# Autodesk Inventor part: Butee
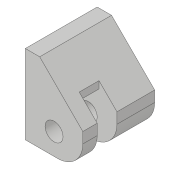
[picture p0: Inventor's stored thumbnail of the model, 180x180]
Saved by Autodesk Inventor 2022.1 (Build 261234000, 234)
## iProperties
Created: 2018-06
Part Number: Butee
Material: Générique
Document SubType Name: Modeling
Designer: Fabian Perrée
Density: 1 g/cm^3
Appearance: Par défaut
Mass: 4.03257 g
Surface Area: 22.3212 cm^2
Volume: 4.03257 cm^3
Author: Fabian Perrée
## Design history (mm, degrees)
sketch "Esquisse1"
  geometry: L1 (0, 0)-(0, 13); L2 (0, 22)-(4, 22); L3 (4, 22)-(11, 15); L4 (16, 10)-(16, 0); L5 (16, 0)-(0, 0); L6 (0, 13)-(11, 13); L7 (11, 13)-(11, 15); L8 (11, 15)-(16, 10); L9 (0, 13)-(0, 22); C1 r 2.5 at (8, 6)
  constraints: 18 end point, 4 perpendicular, 2 parallel, 2 vertical, 1 centre point, 1 collinear, 1 horizontal
  dimensions: "d1" = 4 distance of L2.start L2.end; "d2" = 135 deg angle of L2 L3; "d3" = 5 diameter of C1; "d4" = 6 distance from line of L5 C1.centre; "d5" = 8 distance from line of L1 C1.centre; "d9" = 3 distance from line of C1.centre L7; "d18" = 13 distance between parallel lines of L5 L6; "d20" = 16 distance from line of L2 C1.centre; "d21" = 16 distance between parallel lines of L4 L1
extrude "Extrusion1" new body sketch "Esquisse1" distance "d10" = 4; taper "d12" = 0 deg; dims "d11" = 16, "d13" = 0
extrude "Extrusion2" join sketch "Esquisse1" distance "d14" = 4; taper "d15" = 0 deg
node "Plan de construction1"
node "Plan de construction2"
extrude "Extrusion3" join sketch "Esquisse1" stored distance "d16" = 10; taper "d17" = 0 deg
fillet "Congé1" dims "d22" = 7
node "Solide1"
other parameters: "d19" = 5.5
